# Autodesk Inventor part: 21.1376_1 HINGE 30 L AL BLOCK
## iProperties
Created: 2007-01
Part Number: 21.1376_1 HINGE 30 L AL BLOCK
Document SubType Name: Modeling
Designer: Andy Moles
Material: Aluminum-6061
Density: 2.71 g/cm^3
Mass: 18.3877 g
Surface Area: 42.4483 cm^2
Volume: 6.78512 cm^3
Author: Andy Moles
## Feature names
1. Extrusion1
2. Hole1
